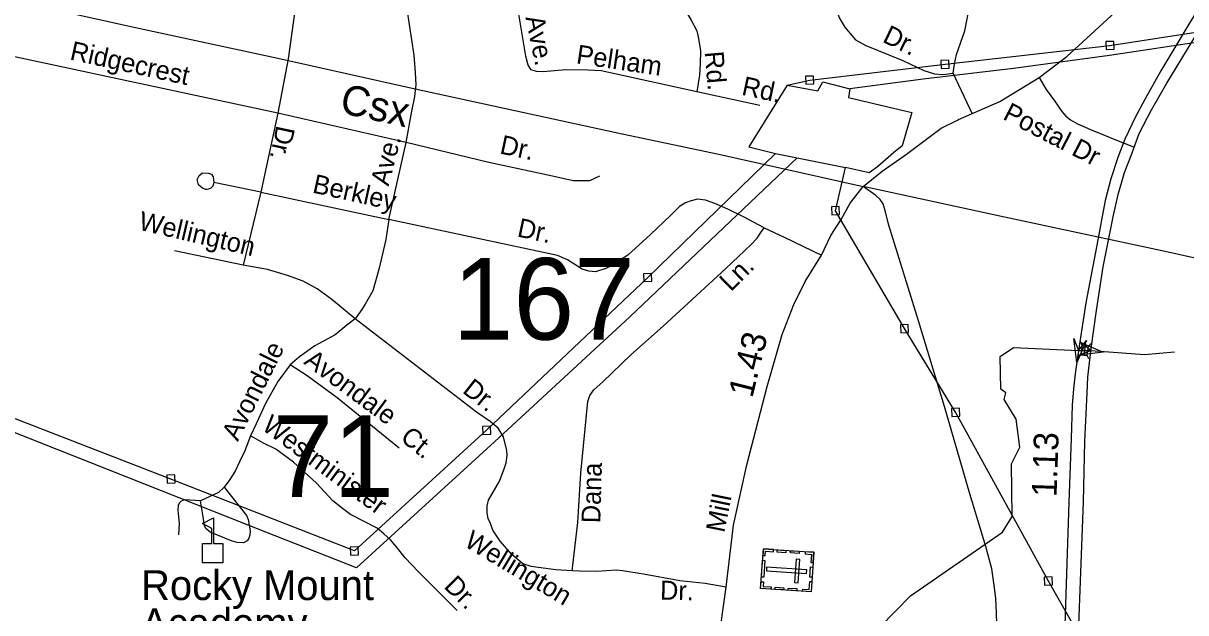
# Model space of a CAD drawing. Extents: x 2220236 to 2384410, y 720751 to 894131.
# Drawn here: x 2341238 to 2347083, y 800919 to 803880 of the extents above; entities that cross this region are included whole.
import ezdxf

# ---------------------------------------------------------------- set-up
doc = ezdxf.new("R2010")
doc.units = 0
doc.layers.add('Default', color=7, linetype='Continuous')

msp = doc.modelspace()

# ---------------------------------------------------------------- linework, layer by layer
at = {"layer": 'Default'}
for p, q in [((2342518.1, 803429.1), (2340877.9, 803778.4)), ((2346010, 803424.1), (2345913.3, 803628.9)), ((2344941.5, 803467.2), (2344624.8, 803535.5)), ((2342518.1, 803429.1), (2342433.1, 803030.8)), ((2343163.5, 803280.6), (2342518.1, 803429.1)), ((2343075.6, 802893.6), (2343163.5, 803280.6)), ((2346708.5, 803302.7), (2346819.5, 803259.8)), ((2345020.4, 803226.3), (2345128.8, 803203.5)), ((2345128.8, 803203.5), (2345371.3, 803154.6)), ((2342433.1, 803030.8), (2342195.8, 803079.9)), ((2342433.1, 803030.8), (2342344.2, 802665.4)), ((2342433.1, 803030.8), (2343075.6, 802893.6)), ((2342344.2, 802665.4), (2341998.4, 802737)), ((2346562.6, 802262), (2346554.1, 802278.8)), ((2346571.1, 802212.7), (2346578.2, 802259.6)), ((2346593.5, 802257.3), (2346606.7, 802270.9)), ((2346542.4, 802201.5), (2346555.5, 802215)), ((2346595.3, 802193.5), (2346586.8, 802210.3))]:
    msp.add_line(p, q, dxfattribs=at)
for points in [[(2331380.2, 806148.5), (2332089.7, 805986.2), (2332785.1, 805833.7), (2333023.7, 805785.1), (2333486.9, 805676.6), (2334090.2, 805538), (2335080.6, 805321.9), (2335954.5, 805132.5), (2336758.3, 804964.2), (2337494, 804803.2), (2338191.7, 804647.6), (2339171.9, 804437.5), (2339987.8, 804257.3), (2340853.6, 804069.8), (2341802, 803859.4), (2342517.6, 803703.9), (2343209.2, 803550.3), (2344249.4, 803324.9), (2344734.6, 803222.8), (2345460.4, 803059.6)], [(2345020.4, 803226.3), (2344378.1, 802602.8), (2343567.7, 801835.2), (2342903.1, 801229.4), (2341981, 801590.2), (2340880.4, 802014.8), (2339974.4, 802379.8), (2338913.6, 802794.9), (2336720, 803652.3), (2335727.9, 804032.2), (2334504.4, 804523.2), (2333596.3, 804882.3), (2333041.1, 805671.2), (2333024.7, 805701.1)], [(2345128.8, 803203.5), (2344288.5, 802405.7), (2343608.3, 801777.6), (2342914.2, 801143.7), (2342458.1, 801324.1), (2341142.3, 801844), (2339390.6, 802528.8), (2337235.2, 803378.6), (2335128.1, 804193), (2333939.1, 804652.4), (2333547.2, 804811.7), (2333272.3, 805222.2), (2333026.4, 805555.2)], [(2345294.2, 804275.1), (2345314.9, 804005.4), (2345325.6, 803943.6), (2345344.2, 803902), (2345368.7, 803860.2), (2345393.1, 803830.5), (2345421.9, 803797.1), (2345475, 803767.6), (2345659.8, 803692.8), (2345765.1, 803643), (2345819.4, 803625.7), (2345861.4, 803622.2), (2345913.3, 803628.9)], [(2345461.4, 803059.4), (2345555.9, 803137.4), (2345679.1, 803223), (2345853.5, 803353.1), (2345934.8, 803393.3), (2345940.3, 803396.2), (2346148.6, 803487.4), (2346346.1, 803608.1), (2346484.7, 803712.5), (2346767.8, 803971.8), (2346960.1, 804172.2), (2347035.4, 804229.4), (2347072, 804246.8), (2347093.5, 804253.5), (2347130.1, 804257.9), (2347170.1, 804252.4), (2347210, 804241.3), (2347293.3, 804194.6)], [(2347293.3, 804194.6), (2347087.3, 803859.3), (2346958, 803640.5), (2346878, 803500.6), (2346829.7, 803409.6), (2346776.4, 803297.4), (2346740.9, 803205.3), (2346706.5, 803098.7), (2346678.2, 802989.8), (2346635.4, 802764.4), (2346581, 802475.7), (2346543.4, 802235.3), (2346526.5, 802118.8), (2346519, 802043.6), (2346511.5, 801961), (2346505.9, 801793.7), (2346494.6, 801474.3), (2346460.8, 800446.4), (2346440.1, 799717.3), (2346423.3, 798959.5), (2346418.3, 798634.2), (2346404, 798402.2)], [(2346475.7, 798398.2), (2346496.3, 798954.6), (2346513.4, 799715.4), (2346530.3, 800457.7), (2346567.8, 801476.1), (2346575.4, 801778.7), (2346586.6, 802023), (2346590.4, 802101.9), (2346607.3, 802246.6), (2346633.7, 802436.9), (2346668.2, 802656.7), (2346719.2, 802916.6), (2346742, 803019.8), (2346775.3, 803129.8), (2346808.6, 803215.3), (2346849.2, 803326.3), (2346910.2, 803445.1), (2346986.9, 803579.5), (2347109.6, 803780.5), (2347236.7, 803994.8), (2347338.9, 804163.5)], [(2344429.2, 804129.5), (2344503, 804029.7), (2344553.8, 803966.3), (2344596.5, 803894.9), (2344625.1, 803841.2), (2344633.7, 803803.3), (2344642.4, 803741.5), (2344641.1, 803675.6), (2344637.8, 803619.4), (2344624.8, 803535.5)], [(2344624.8, 803535.5), (2344143.7, 803641.5), (2344077.7, 803644.8), (2343965.8, 803645.4), (2343852, 803636), (2343817.9, 803637.6), (2343791.8, 803645.3), (2343777.6, 803669.1), (2343764.9, 803715), (2343711.1, 804038.2)], [(2345913.3, 803628.9), (2345920.3, 803676.1), (2345930.1, 803723.3), (2345971.4, 803841.3), (2345999.1, 803979.7), (2346016.3, 804031.9), (2346020, 804060)], [(2342605.9, 803953.4), (2342569.6, 803700.7), (2342518.1, 803429.1)], [(2343163.5, 803280.6), (2343192.6, 803438.2), (2343207.5, 803512.4), (2343213, 803570.5), (2343210.2, 803632.4), (2343203.1, 803720.1), (2343167.8, 803950.8)], [(2345078.2, 803568.8), (2345192, 803594.2), (2345872.9, 803674.3), (2346701.4, 803768.3), (2347318, 803863.7)], [(2347190.8, 803792.1), (2346700, 803718.2), (2346216.9, 803652.5), (2345761.7, 803599.1), (2345394.5, 803550.7)], [(2346682.2, 803747.5), (2346722.2, 803749.1), (2346720.5, 803789.1), (2346680.6, 803787.5), (2346682.2, 803747.5)], [(2345853.7, 803653.5), (2345893.7, 803655.1), (2345892, 803695), (2345852.1, 803693.4), (2345853.7, 803653.5)], [(2345078.2, 803568.8), (2344886, 803258.6), (2345020.4, 803226.3)], [(2345078.2, 803568.8), (2345232.6, 803540.7), (2345258.1, 803584.9), (2345394.5, 803550.7)], [(2345172.9, 803573.4), (2345212.8, 803575.1), (2345211.2, 803615), (2345171.3, 803613.4), (2345172.9, 803573.4)], [(2346346.1, 803608.1), (2346380.3, 803546.5), (2346423.1, 803490), (2346459, 803436.9), (2346479.6, 803413), (2346503.5, 803394.1), (2346537.7, 803375.3), (2346604.4, 803346.2), (2346693.4, 803308.6), (2346708.5, 803302.7)], [(2345394.5, 803550.7), (2345386.9, 803506.6), (2345705.7, 803432.3), (2345657.7, 803263.9), (2345614.1, 803229.3), (2345533.2, 803158.4), (2345491.4, 803127.9), (2345371.3, 803154.6)], [(2344135.6, 803111), (2344085.7, 803088.6), (2344003, 803088.6), (2343899.7, 803111), (2343579.5, 803179.9), (2343163.5, 803280.6)], [(2348707.3, 791564.5), (2348681.9, 792186.1), (2348644.1, 792827.5), (2348595.1, 793420.7), (2348557.5, 794054), (2348519.6, 794701.4), (2348483.4, 795216.7), (2348445.1, 795757.9), (2348415.6, 796367.4), (2348363.4, 797058.6), (2348322, 797681.9), (2348023.9, 798200.2), (2347737.8, 798710.5), (2347371.9, 799369.8), (2346969.9, 800062.7), (2346651.1, 800622.8), (2346391.8, 801077.6), (2345925.8, 801925.5), (2345668.8, 802346.4), (2345321.9, 802938.1), (2345371.3, 803154.6)], [(2342195.8, 803079.9), (2342191.9, 803061.9), (2342180, 803049.6), (2342162.2, 803045.5), (2342154.2, 803045.4), (2342140.1, 803051.2), (2342119.8, 803069), (2342113.5, 803094.9), (2342123.3, 803114.9), (2342137.2, 803127.1), (2342141.2, 803129.3), (2342169.2, 803127.6), (2342185.3, 803121.7), (2342193.5, 803107.8), (2342195.8, 803079.9)], [(2344684.2, 800569.1), (2344692.2, 800589.2), (2344713.4, 800663.5), (2344730.3, 800749.6), (2344772.5, 801047.6), (2344809.3, 801358.3), (2344876, 801661.2), (2344978.6, 802054.9), (2345053.1, 802315.9), (2345112.9, 802466.5), (2345169.4, 802582.9), (2345250.6, 802715.5), (2345298.5, 802813.1), (2345349.8, 802893.5), (2345396, 802975.7), (2345461.4, 803059.4)], [(2348912.6, 802275.3), (2348836.4, 802300.4), (2348767.9, 802325.6), (2348671.7, 802354.5), (2348563.3, 802387.1), (2348449.1, 802411.7), (2348268.7, 802453.5), (2348100.4, 802489.5), (2347879.7, 802536.9), (2347420.7, 802635.4), (2346979.7, 802734), (2346171.9, 802906.1), (2345460.4, 803059.6)], [(2346161.4, 799953.1), (2346131.9, 800916.5), (2346127, 800992.3), (2346118.1, 801068.2), (2346107.2, 801140), (2346077.8, 801251.6), (2345996.7, 801516.6), (2345869.4, 801954.8), (2345738.4, 802385.2), (2345588.5, 802871.1), (2345573.8, 802932.9), (2345561.4, 802972.9), (2345547.1, 802994.7), (2345524.8, 803014.4), (2345461.4, 803059.4)], [(2344963.3, 802852.4), (2344858.9, 802907.2), (2344780.2, 802946.6), (2344715.2, 802974), (2344669.1, 802991.1), (2344628, 802996.2), (2344595.5, 802987.6), (2344568.1, 802977.4), (2344537.4, 802958.6), (2344492.9, 802914.1), (2344392, 802818.2), (2344277.4, 802715.5), (2344202.1, 802665.9), (2344167.9, 802648.8), (2344114.9, 802631.7), (2344082.4, 802635.1), (2344048.2, 802645.3), (2343973.8, 802690.7), (2343924.2, 802712.9), (2343075.6, 802893.6)], [(2345302.7, 802917.3), (2345342.7, 802918.9), (2345341, 802958.9), (2345301.1, 802957.2), (2345302.7, 802917.3)], [(2343075.6, 802893.6), (2343061.2, 802793.3), (2343028.5, 802650), (2342995.8, 802535.4), (2342958.2, 802469.6), (2342940.5, 802441.5), (2342906.8, 802395.1)], [(2343998.8, 801129.1), (2344025.9, 801372), (2344041.3, 801620.1), (2344077.3, 801979.6), (2344087.5, 802010.4), (2344106.3, 802037.8), (2344152.5, 802078.8), (2344292.8, 802214), (2344455.3, 802357.8), (2344770, 802648.8), (2344898.3, 802768.6), (2344927.3, 802801.1), (2344946.2, 802828.5), (2344963.3, 802852.4)], [(2344963.3, 802852.4), (2345064.2, 802806.2), (2345250.6, 802715.5)], [(2342906.8, 802395.1), (2342790.2, 802491.4), (2342716.5, 802546.6), (2342644.9, 802583.5), (2342567.2, 802612.2), (2342466.9, 802642.9), (2342344.2, 802665.4)], [(2344359, 802582), (2344398.9, 802583.6), (2344397.3, 802623.6), (2344357.3, 802622), (2344359, 802582)], [(2342906.8, 802395.1), (2342865.5, 802362.6), (2342806.1, 802313.9), (2342704.9, 802258.8), (2342627.5, 802203.8), (2342580.1, 802163.2)], [(2343998.8, 801129.1), (2343915.9, 801133.7), (2343827.9, 801146.5), (2343791.8, 801150.1), (2343749.6, 801163.6), (2343695, 801211), (2343636.3, 801278.2), (2343599.6, 801333.7), (2343587.2, 801367.6), (2343575, 801391.5), (2343570.7, 801419.4), (2343570.2, 801455.4), (2343577.9, 801483.5), (2343632.7, 801580.2), (2343656, 801642.3), (2343665.6, 801672.5), (2343671.1, 801708.6), (2343668.9, 801734.5), (2343652.1, 801802.2), (2343625.5, 801846), (2343585.1, 801879.3), (2343516.6, 801926.6), (2342906.8, 802395.1)], [(2345649.6, 802325.6), (2345689.5, 802327.2), (2345687.9, 802367.2), (2345648, 802365.5), (2345649.6, 802325.6)], [(2345468.4, 800767.2), (2345698.4, 801003.1), (2346161.4, 801324), (2346210.5, 801401.5), (2346207.4, 801667.2), (2346248.4, 801750.9), (2346229.5, 801891.3), (2346170.5, 801990.6), (2346178.5, 802023.7), (2346152.4, 802042.4), (2346150.4, 802206.4), (2346216.4, 802251.8), (2346543.4, 802235.3), (2346574.7, 802236.2), (2346606.2, 802236.2), (2346875.5, 802216.3), (2347026.6, 802229.4)], [(2342580.1, 802163.2), (2342519.1, 802080.5), (2342456.3, 801969.9), (2342409.7, 801867.4), (2342380.4, 801806.9)], [(2343128.8, 801746.1), (2342815.9, 801998.2), (2342666.6, 802108.4), (2342580.1, 802163.2)], [(2345906.7, 801904.7), (2345946.6, 801906.3), (2345945, 801946.3), (2345905, 801944.7), (2345906.7, 801904.7)], [(2343548.5, 801814.4), (2343588.5, 801816.1), (2343586.9, 801856), (2343546.9, 801854.4), (2343548.5, 801814.4)], [(2342380.4, 801806.9), (2342353.2, 801732.6), (2342325.9, 801676.3), (2342303.6, 801629.4), (2342277.2, 801588.4), (2342249.3, 801548.8)], [(2343420.6, 800929.8), (2343226.2, 801123.4), (2343158.7, 801194), (2343113.7, 801250.7), (2343085.4, 801285.7), (2343052, 801315.7), (2343017, 801344.1), (2342883.7, 801412.4), (2342842.6, 801442.7), (2342794.1, 801480.1), (2342713.2, 801569), (2342597.8, 801675.6), (2342509.1, 801740.6), (2342446.7, 801769.8), (2342380.4, 801806.9)], [(2341961.9, 801569.4), (2342001.8, 801571), (2342000.2, 801610.9), (2341960.2, 801609.3), (2341961.9, 801569.4)], [(2342249.3, 801548.8), (2342220.8, 801522), (2342130.2, 801481.5)], [(2342249.3, 801548.8), (2342361, 801406.3), (2342369.2, 801386.4), (2342379.9, 801330.4), (2342378.2, 801308.6), (2342372.4, 801292.5), (2342364.5, 801280.4), (2342345.4, 801269.1), (2342314.6, 801271.8), (2342288.6, 801277.5), (2342178, 801324.2), (2342155.9, 801341.9), (2342147.6, 801359.8), (2342145.4, 801389.7), (2342130.2, 801481.5)], [(2342130.2, 801481.5), (2342048.3, 801485.1), (2342032.4, 801478.8), (2342022.6, 801468.8), (2342016.7, 801456.8), (2342015.3, 801433.8), (2342021.7, 801367.3), (2342019, 801310)], [(2342884, 801208.7), (2342923.9, 801210.3), (2342922.3, 801250.2), (2342882.3, 801248.6), (2342884, 801208.7)], [(2344772.5, 801047.6), (2344666.5, 801064.8), (2344539.9, 801078.4), (2344356.1, 801112.9), (2344251.8, 801129.6), (2344219.8, 801133.3), (2344121.9, 801126.1), (2344034, 801127.2), (2343998.8, 801129.1)], [(2346372.7, 801056.8), (2346412.6, 801058.4), (2346411, 801098.3), (2346371, 801096.7), (2346372.7, 801056.8)]]:
    msp.add_lwpolyline(points, dxfattribs=at)
for points in [[(2346583, 802286.8), (2346534.4, 802175), (2346520.6, 802296.2), (2346543.4, 802235.3)], [(2346554.4, 802275.4), (2346666.6, 802227.6), (2346545.6, 802212.9), (2346606.2, 802236.2)], [(2346586.8, 802210.3), (2346593.8, 802257.3), (2346562.6, 802262), (2346555.5, 802215)], [(2342140.1, 801169.1), (2342140.1, 801267.1), (2342186.1, 801267.1), (2342186.1, 801342.1), (2342139.1, 801366.4), (2342195.7, 801395.6), (2342195.7, 801267.1), (2342241.8, 801267.1), (2342241.8, 801169.1)], [(2345213.1, 801222.2), (2345199.7, 801023.6), (2344945.6, 801040.8), (2344959.1, 801239.4)], [(2344956.9, 801206.4), (2344968.4, 801205.6), (2344969.8, 801227.6), (2345010.2, 801224.9), (2345010.9, 801236), (2344959.1, 801239.5)], [(2345028.9, 801234.7), (2345072.1, 801231.8), (2345071.3, 801220.4), (2345028.1, 801223.4)], [(2345095.9, 801230.2), (2345139.1, 801227.2), (2345138.4, 801215.9), (2345095.2, 801218.8)], [(2345169.9, 801225.1), (2345169.2, 801213.8), (2345201.3, 801211.6), (2345198.5, 801171.2), (2345209.6, 801170.4), (2345213.1, 801222.2)], [(2344966.7, 801181.3), (2344960.9, 801096.7), (2344949.5, 801097.4), (2344955.3, 801182.1)], [(2345142.5, 801186.1), (2345123.8, 801187.3), (2345115.9, 801069.9), (2345134.5, 801068.6)], [(2345176.5, 801115.4), (2345177.8, 801134), (2344975.5, 801147.8), (2344974.2, 801129.1)], [(2345208.1, 801148.3), (2345204.6, 801096.6), (2345193.2, 801097.4), (2345196.7, 801149.1)], [(2344947.9, 801073.8), (2344959.3, 801073.1), (2344957.8, 801051.1), (2344998.2, 801048.4), (2344997.4, 801037.3), (2344945.6, 801040.8)], [(2345156.4, 801026.4), (2345157.2, 801037.8), (2345189.3, 801035.6), (2345192, 801076), (2345203.1, 801075.3), (2345199.6, 801023.5)], [(2345018.5, 801047.2), (2345061.7, 801044.3), (2345060.9, 801033), (2345017.7, 801035.9)], [(2345084.3, 801042.8), (2345127.5, 801039.8), (2345126.7, 801028.5), (2345083.5, 801031.4)]]:
    msp.add_lwpolyline(points, close=True, dxfattribs=at)

# ---------------------------------------------------------------- texts
for s, height, rotation, p in [('Ave.', 95, 281.58358, (2343763, 803909.5)), ('Dr.', 95, 334.09267, (2345553.1, 803788.4)), ('Ridgecrest', 95, 347.63715, (2341468.6, 803698.5)), ('Pelham', 95, 351.55851, (2344015.1, 803678.9)), ('Rd.', 95, 274.84065, (2344663.9, 803736)), ('Csx', 150, 347.4783, (2342824, 803431.8)), ('Rd.', 95, 347.82979, (2344845.7, 803521.4)), ('Postal Dr', 95, 332.59238, (2346157.8, 803400.7)), ('Dr.', 95, 257.98396, (2342512.4, 803370.3)), ('Ave.', 95, 75.4954, (2343075, 803058.5)), ('Dr.', 95, 347.88618, (2343629.8, 803226.5)), ('Berkley', 95, 347.5522, (2342688, 803030)), ('Wellington', 95, 346.86079, (2341813.7, 802844)), ('Dr.', 95, 348.107, (2343717.5, 802809.3)), ('Ln.', 95, 44.51916, (2344795.2, 802528.8)), ('Avondale', 95, 63.42474, (2342316.8, 801776.2)), ('1.43', 125, 76.02086, (2344903.2, 801994.2)), ('Avondale', 95, 323.56873, (2342644.5, 802171.9)), ('Dr.', 95, 321.66125, (2343441.7, 802027.7)), ('Westminister', 95, 323.51772, (2342432.1, 801842.7)), ('Ct.', 95, 321.14205, (2343128.7, 801788.3)), ('1.13', 125, 87.97971, (2346432.9, 801498.8)), ('Dana', 95, 88.49625, (2344139.5, 801367.7)), ('Mill', 95, 78.49661, (2344762.3, 801317.4)), ('Wellington', 95, 329.10792, (2343449.4, 801256.2)), ('Dr.', 95, 315.11821, (2343348.9, 801047.5)), ('Dr.', 95, 358.54478, (2344439.1, 800985.2))]:
    msp.add_text(s, height=height, rotation=rotation, dxfattribs=at).set_placement(p)
for s, height, p in [('167', 410.1, (2343397.7, 802290.4)), ('71', 410.1, (2342492.2, 801500.7)), ('Rocky Mount', 150, (2341831.2, 800982.3)), ('Academy', 150, (2341831.2, 800791.3))]:
    msp.add_text(s, height=height, dxfattribs=at).set_placement(p)

doc.saveas('drawing.dxf')
